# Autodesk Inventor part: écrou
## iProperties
Created: 2002-06
Part Number: écrou
Material: Par défaut
Document SubType Name: Modélisation
Designer: REVEST Pierre
Control State: 0
Master: False
Checked Out: False
Shininess: 78.0
Length Units: 11269
Angle Units: 11279
Time Units: 11290
Mass Units: 11283
Length Display Precision: 3
Angle Display Precision: 2
Density: 0.0
Volumn: 0.0
Area: 0.0
PropertySet Name: Model Information
Author: REVEST Pierre
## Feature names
1. Extrusion1
2. Extrusion2
3. Extrusion3
4. Chanfrein1 [Chamfer]
5. Perçage1 [Hole]
